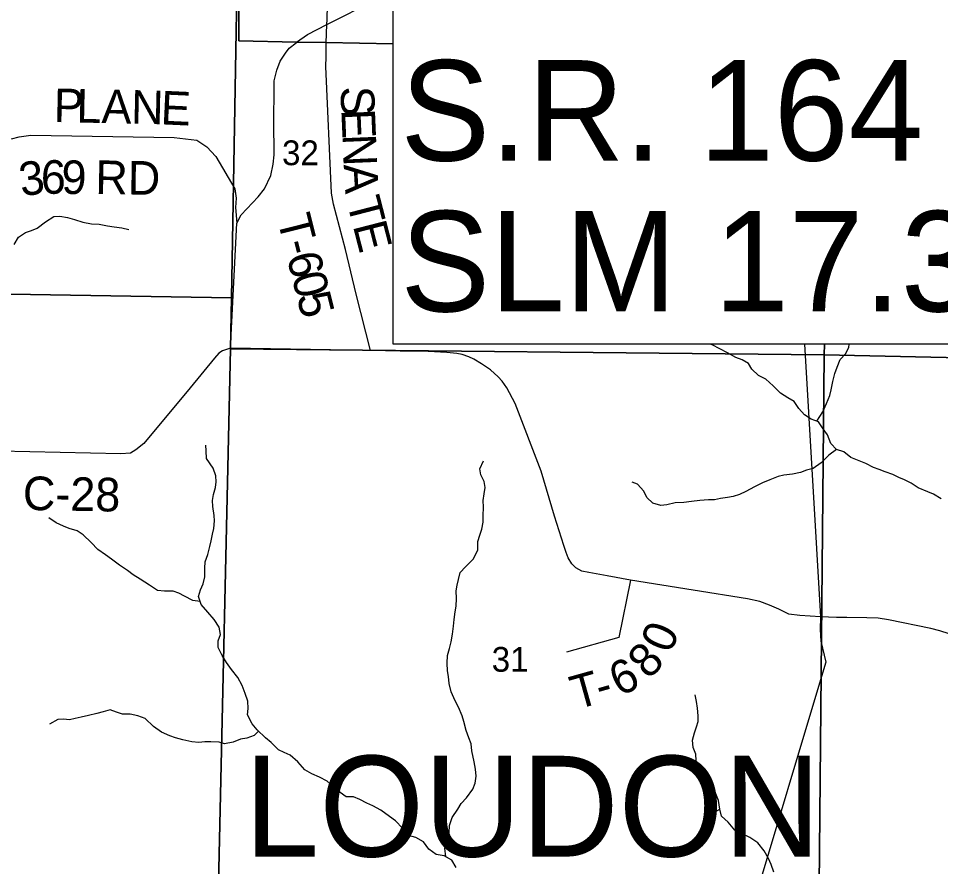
# Model space of a CAD drawing. Extents: x -20.5 to 34, y -66 to 23.9.
# Drawn here: x 5.573 to 7.132, y 17.496 to 18.93 of the extents above; entities that cross this region are included whole.
import ezdxf

# ---------------------------------------------------------------- set-up
doc = ezdxf.new("R2010")
doc.units = 0
for name, color, linetype in [('Default', 7, 'Continuous'), ('GM_X_County_Text', 7, 'Continuous'), ('GM_X_Minor_Lake', 7, 'Continuous'), ('GM_X_Minor_River', 7, 'Continuous'), ('GM_X_Minor_River_Text', 7, 'Continuous'), ('GM_X_Section_Text', 7, 'Continuous'), ('GM_X_State_Location', 7, 'Continuous'), ('GM_X_State_Route', 7, 'Continuous'), ('GM_X_Township_Road_Text', 7, 'Continuous'), ('GM_X_Township_Text', 7, 'Continuous'), ('SH_Text', 7, 'Continuous')]:
    doc.layers.add(name, color=color, linetype=linetype)

msp = doc.modelspace()

# ---------------------------------------------------------------- linework, layer by layer
at = {"layer": 'Default'}
for points in [[(8.3774, 18.8452), (8.7292, 18.8379), (8.9, 18.8361), (8.9, 20.9), (2.1, 20.9), (2.1, 19.024), (2.1138, 19.0238), (2.8866, 19.0123), (2.9847, 19.0125), (3.3332, 19.0103), (5.1839, 18.9738), (5.2343, 18.9736), (5.2893, 18.9731), (5.9456, 18.969), (5.9451, 18.8918), (6.0429, 18.8899), (6.0928, 18.889), (6.2064, 18.8869)], [(6.2064, 18.8869), (6.0928, 18.889), (6.0429, 18.8899), (5.9451, 18.8918), (5.9456, 18.969), (5.2893, 18.9731), (5.2343, 18.9736), (5.1839, 18.9738), (3.3332, 19.0103), (2.9847, 19.0125), (2.8866, 19.0123), (2.8861, 18.9025), (2.8826, 18.5075), (2.8801, 18.0269), (2.88, 18.0245)]]:
    msp.add_lwpolyline(points, dxfattribs=at)
at = {"layer": 'GM_X_County_Text'}
for p, q in [((6.9024, 18.3792), (6.9292, 17.9178)), ((6.9226, 17.7886), (6.6781, 16.9745))]:
    msp.add_line(p, q, dxfattribs=at)
for points in [[(6.0946, 18.9277), (6.0951, 18.9521), (6.0953, 18.9667), (6.0907, 18.9815), (6.0603, 19.0257), (6.0466, 19.0569), (6.0218, 19.0744)], [(6.093, 18.8874), (6.093, 18.8885), (6.0945, 18.9196), (6.0946, 18.9277)], [(6.1683, 18.3682), (6.1436, 18.4633), (6.1256, 18.5392), (6.1054, 18.6158), (6.102, 18.6341), (6.0926, 18.8484), (6.093, 18.865), (6.093, 18.8874)], [(5.5609, 18.7262), (5.5738, 18.7296), (5.5938, 18.7323), (5.8358, 18.7284), (5.8745, 18.7238), (5.8914, 18.7124), (5.9062, 18.696), (5.9388, 18.6418), (5.9411, 18.6258), (5.94, 18.6103), (5.9418, 18.5834)], [(6.6081, 17.9801), (6.5883, 17.8829), (6.4997, 17.8579)], [(6.9292, 17.9178), (6.9287, 17.8963), (6.9296, 17.8766), (6.9329, 17.8649), (6.9384, 17.841), (6.9226, 17.7886)]]:
    msp.add_lwpolyline(points, dxfattribs=at)
at = {"layer": 'GM_X_Minor_Lake'}
for points in [[(4.9304, 19.491), (5.9508, 19.4767), (5.9493, 19.3913), (5.9332, 18.4574), (4.9118, 18.4742)], [(4.9118, 18.4742), (5.9332, 18.4574), (5.9313, 18.3709), (5.9103, 17.4412), (4.9246, 17.4548), (4.898, 17.4556)], [(6.9356, 18.3607), (6.9259, 17.3432), (5.9397, 17.3613), (5.9082, 17.3615), (5.9103, 17.4412), (5.9313, 18.3709)], [(7.9409, 18.3387), (7.9284, 17.3287), (7.0924, 17.3404), (6.9259, 17.3432), (6.9356, 18.3607)]]:
    msp.add_lwpolyline(points, close=True, dxfattribs=at)
for points in [[(6.9358, 18.3792), (6.9356, 18.3607), (5.9313, 18.3709), (5.9332, 18.4574), (5.9493, 19.3913), (6.9446, 19.3763), (6.9427, 19.1628)], [(7.9415, 18.3792), (7.9409, 18.3387), (6.9356, 18.3607), (6.9358, 18.3792)]]:
    msp.add_lwpolyline(points, dxfattribs=at)
at = {"layer": 'GM_X_Minor_River'}
for points in [[(6.7259, 17.649), (6.7273, 17.6343), (6.7301, 17.6256), (6.7356, 17.609), (6.7395, 17.5995), (6.7419, 17.592), (6.7477, 17.5864), (6.7589, 17.5926)], [(6.7589, 17.5926), (6.7568, 17.607), (6.7521, 17.6187), (6.7474, 17.6292), (6.7381, 17.642), (6.7259, 17.649)]]:
    msp.add_lwpolyline(points, dxfattribs=at)
at = {"layer": 'GM_X_Minor_River_Text'}
for points in [[(5.5652, 18.5474), (5.5726, 18.56), (5.5846, 18.5677), (5.5948, 18.5713), (5.6045, 18.5753), (5.6184, 18.5857), (5.6323, 18.5946), (5.6428, 18.5956), (5.6557, 18.5931), (5.6675, 18.5899), (5.6816, 18.5852), (5.696, 18.5823), (5.7093, 18.5818), (5.7233, 18.579), (5.7347, 18.5772), (5.7476, 18.5755), (5.7593, 18.5731)], [(7.1335, 18.1176), (7.1205, 18.1254), (7.1106, 18.129), (7.0946, 18.136), (7.0824, 18.1441), (7.0713, 18.1496), (7.0618, 18.1537), (7.0519, 18.1588), (7.0389, 18.1632), (7.0287, 18.1668), (7.0192, 18.1705), (7.0062, 18.1771), (6.9948, 18.1815), (6.9807, 18.1873), (6.9688, 18.197), (6.9563, 18.2006), (6.9466, 18.2107), (6.9411, 18.2254), (6.9338, 18.2356), (6.926, 18.2476), (6.9135, 18.2519), (6.9024, 18.2597), (6.8924, 18.2702), (6.8846, 18.2822), (6.8739, 18.2881), (6.8617, 18.2963), (6.849, 18.3082), (6.8368, 18.3198), (6.8242, 18.3261), (6.8134, 18.3365), (6.8076, 18.3463), (6.7969, 18.3522), (6.7859, 18.3566), (6.7717, 18.3643), (6.7588, 18.3713), (6.7462, 18.3776), (6.7416, 18.3792)], [(6.9233, 18.2485), (6.9333, 18.2644), (6.9392, 18.2785), (6.945, 18.2922), (6.9471, 18.3018), (6.9503, 18.3158), (6.9535, 18.3295), (6.9572, 18.3402), (6.9626, 18.3528), (6.9716, 18.3628), (6.9771, 18.3731), (6.9776, 18.3792)], [(5.8818, 17.9385), (5.8774, 17.9521), (5.8803, 17.9635), (5.8851, 17.9738), (5.8879, 17.9856), (5.8881, 18), (5.8887, 18.011), (5.893, 18.0232), (5.8966, 18.0366), (5.8987, 18.0465), (5.9008, 18.0575), (5.9029, 18.067), (5.9043, 18.0799), (5.9034, 18.0894), (5.9016, 18.1042), (5.9011, 18.1144), (5.9024, 18.1246), (5.9057, 18.1365), (5.907, 18.1463), (5.9065, 18.1562), (5.9021, 18.169), (5.8905, 18.1855), (5.8899, 18.1988), (5.8898, 18.2083)], [(6.9563, 18.2006), (6.9435, 18.1913), (6.9305, 18.1782), (6.9166, 18.1689), (6.9057, 18.1657), (6.8952, 18.1621), (6.882, 18.1589), (6.8672, 18.1576), (6.8574, 18.1551), (6.8435, 18.1496), (6.8311, 18.1445), (6.8176, 18.1375), (6.803, 18.1296), (6.7924, 18.1249), (6.7815, 18.1214), (6.7717, 18.1197), (6.76, 18.118), (6.7502, 18.1159), (6.7396, 18.1154), (6.7249, 18.1144), (6.7113, 18.1127), (6.698, 18.1114), (6.6833, 18.1104), (6.6693, 18.1071), (6.6591, 18.1062), (6.6458, 18.1102), (6.6355, 18.1195), (6.6304, 18.1304), (6.62, 18.1424), (6.6105, 18.1453)], [(6.2954, 17.5121), (6.2941, 17.5268), (6.3023, 17.5402), (6.3009, 17.5523), (6.3015, 17.5648), (6.3062, 17.5785), (6.3158, 17.5927), (6.3217, 17.6023), (6.3307, 17.6119), (6.3414, 17.6265), (6.3454, 17.6368), (6.3468, 17.6486), (6.3458, 17.6603), (6.3434, 17.6728), (6.3397, 17.6913), (6.3384, 17.7031), (6.3344, 17.7132), (6.3297, 17.7257), (6.3257, 17.7408), (6.3233, 17.7506), (6.317, 17.7653), (6.3115, 17.7759), (6.3045, 17.7909), (6.3012, 17.8053), (6.3003, 17.8167), (6.2986, 17.8265), (6.2977, 17.8394), (6.2986, 17.8523), (6.3015, 17.8645), (6.3047, 17.8755), (6.3068, 17.8884), (6.3085, 17.9021), (6.3094, 17.9131), (6.3111, 17.9261), (6.3129, 17.9359), (6.3134, 17.9488), (6.3132, 17.9617), (6.3146, 17.9712), (6.3167, 17.9811), (6.3199, 17.9929), (6.3289, 18.0026), (6.3423, 18.016), (6.3496, 18.031), (6.3498, 18.0454), (6.353, 18.0557), (6.3567, 18.0663), (6.3584, 18.0777), (6.3586, 18.0884), (6.3591, 18.1032), (6.3589, 18.1145), (6.3603, 18.1259), (6.362, 18.1366), (6.3603, 18.1468), (6.3549, 18.1577), (6.3532, 18.1679), (6.3591, 18.1817)], [(5.8802, 17.9436), (5.8673, 17.9455), (5.8536, 17.9528), (5.8437, 17.958), (5.8342, 17.9613), (5.8198, 17.961), (5.8077, 17.9624), (5.7943, 17.9713), (5.7786, 17.9813), (5.7668, 17.9891), (5.7572, 17.9961), (5.7438, 18.0054), (5.73, 18.0151), (5.7201, 18.0225), (5.7067, 18.0318), (5.6955, 18.0437), (5.6821, 18.0564), (5.6718, 18.0631), (5.6585, 18.0674), (5.649, 18.0711), (5.6364, 18.077), (5.6238, 18.0851)], [(6.3132, 17.4941), (6.3054, 17.5065), (6.2928, 17.5135), (6.2792, 17.5159), (6.2665, 17.5248), (6.258, 17.5376), (6.2447, 17.5446), (6.2325, 17.5482), (6.2225, 17.5602), (6.2102, 17.5729), (6.2002, 17.58), (6.1857, 17.5911), (6.1723, 17.5981), (6.1621, 17.6029), (6.1498, 17.6092), (6.1392, 17.6135), (6.1267, 17.6137), (6.1167, 17.6208), (6.1049, 17.6309), (6.0949, 17.6398), (6.0819, 17.6468), (6.069, 17.6523), (6.0571, 17.6593), (6.0452, 17.6728), (6.0322, 17.684), (6.0222, 17.6884), (6.0127, 17.6928), (6, 17.7051), (5.9905, 17.7133), (5.9763, 17.7268), (5.9682, 17.7369), (5.9603, 17.7523), (5.9613, 17.7629), (5.9604, 17.7751), (5.956, 17.7883), (5.9509, 17.8015), (5.9435, 17.815), (5.9331, 17.8285), (5.9246, 17.8405), (5.9172, 17.8525), (5.9106, 17.8657), (5.9104, 17.8771), (5.9144, 17.8878), (5.9123, 17.9006), (5.9038, 17.9134), (5.893, 17.9258), (5.8818, 17.9385)], [(6.8502, 17.4863), (6.8459, 17.4991), (6.8416, 17.5089), (6.8338, 17.5221), (6.8234, 17.5356), (6.8096, 17.5448), (6.7967, 17.5507), (6.7841, 17.557), (6.7733, 17.5708), (6.7618, 17.5809), (6.7589, 17.5926), (6.7568, 17.607), (6.7521, 17.6187), (6.7474, 17.6292), (6.7381, 17.642), (6.7259, 17.649), (6.7216, 17.6607), (6.7187, 17.6751), (6.7182, 17.6857), (6.7138, 17.697), (6.7129, 17.7091), (6.7161, 17.7217), (6.7194, 17.7316), (6.7222, 17.7411), (6.7225, 17.7506), (6.7211, 17.7635), (6.7195, 17.7745), (6.7174, 17.7858)], [(5.9789, 17.7242), (5.9715, 17.7172), (5.9591, 17.7128), (5.9481, 17.7108), (5.9357, 17.706), (5.9214, 17.7032), (5.9119, 17.7057), (5.8979, 17.7066), (5.888, 17.7064), (5.8778, 17.7051), (5.8657, 17.7065), (5.8505, 17.7097), (5.8383, 17.7133), (5.8285, 17.7165), (5.8147, 17.7228), (5.8013, 17.7324), (5.7868, 17.7459), (5.7746, 17.7506), (5.7617, 17.7531), (5.7484, 17.7532), (5.7385, 17.7565), (5.7275, 17.7605), (5.7158, 17.7573), (5.7053, 17.7545), (5.6913, 17.7509), (5.6789, 17.748), (5.6687, 17.746), (5.6589, 17.7439), (5.649, 17.7445), (5.6392, 17.744), (5.6253, 17.7362)]]:
    msp.add_lwpolyline(points, dxfattribs=at)
at = {"layer": 'GM_X_State_Route'}
for points in [[(6.0422, 18.8887), (6.0431, 18.8894), (6.0615, 18.9024), (6.0945, 18.9196), (6.1772, 18.9617), (6.1887, 18.9656), (6.1991, 18.9679), (6.2064, 18.9689)], [(5.9311, 18.3724), (5.9418, 18.5834), (5.9493, 18.5975), (5.9778, 18.6281), (5.9886, 18.6418), (5.9993, 18.6641), (6.0036, 18.6833), (6.0054, 18.6992), (6.0048, 18.756), (6.0051, 18.8103), (6.0052, 18.824), (6.0095, 18.8424), (6.0152, 18.8573), (6.0241, 18.8712), (6.0308, 18.8796), (6.0422, 18.8887)], [(7.1468, 17.8888), (7.1309, 17.8941), (7.1159, 17.8979), (7.0441, 17.913), (7.0269, 17.9156), (7.0077, 17.9162), (6.9738, 17.9165), (6.9561, 17.9168), (6.9292, 17.9178), (6.8941, 17.9198), (6.8756, 17.9226), (6.8586, 17.9307), (6.8432, 17.9377), (6.8264, 17.9436), (6.8057, 17.9483), (6.714, 17.9632), (6.6081, 17.9801), (6.5683, 17.987), (6.5373, 17.9928), (6.5256, 17.9953), (6.5154, 18.0009), (6.5087, 18.0074), (6.5025, 18.0174), (6.499, 18.0265), (6.4952, 18.0384), (6.4791, 18.0878), (6.457, 18.1639), (6.4129, 18.2786), (6.3989, 18.3053), (6.3907, 18.3165), (6.3843, 18.3236), (6.3713, 18.3353), (6.3561, 18.3455), (6.3427, 18.3533), (6.3343, 18.3574), (6.3232, 18.3612), (6.3139, 18.3632), (6.2974, 18.3649), (6.2658, 18.3664), (6.2181, 18.3671), (6.1683, 18.3682), (5.9311, 18.3724), (5.9176, 18.3679), (5.9115, 18.3638), (5.9044, 18.3553), (5.8631, 18.3052), (5.7845, 18.2107), (5.7712, 18.2), (5.7619, 18.1946), (5.746, 18.1933), (5.4374, 18.2004)]]:
    msp.add_lwpolyline(points, dxfattribs=at)
at = {"layer": 'SH_Text'}
msp.add_lwpolyline([(6.2064, 19.1628), (8.3774, 19.1628), (8.3774, 18.3792), (6.2064, 18.3792)], close=True, dxfattribs=at)

# ---------------------------------------------------------------- texts
at = {"layer": 'GM_X_Section_Text'}
for s, height, rotation, p in [('P', 0.0568, 358.8311, (5.6319, 18.7546)), ('S', 0.0568, 272.3954, (6.1171, 18.8142)), ('L', 0.0568, 358.8321, (5.6702, 18.7538)), ('A', 0.0568, 358.8306, (5.7127, 18.7529)), ('N', 0.0568, 358.7595, (5.7627, 18.7519)), ('E', 0.0568, 357.3891, (5.8123, 18.7508)), ('E', 0.0568, 272.3982, (6.1187, 18.7759)), ('N', 0.0568, 272.4002, (6.1205, 18.7334)), ('3', 0.0568, 8.1555, (5.5778, 18.6287)), ('6', 0.0568, 359.3339, (5.6102, 18.6335)), ('9', 0.0568, 359.2012, (5.6451, 18.6331)), ('RD', 0.05682, 359.0118, (5.7023, 18.6331)), ('A', 0.0568, 273.2783, (6.1227, 18.6825)), ('T', 0.0568, 284.521, (6.1274, 18.6206)), ('T', 0.0568, 284.0888, (6.0098, 18.5914)), ('E', 0.0568, 284.4229, (6.138, 18.5795)), ('-', 0.0568, 284.099, (6.0202, 18.5502)), ('6', 0.0568, 284.1255, (6.0258, 18.5278)), ('0', 0.0568, 284.1938, (6.0343, 18.494)), ('5', 0.0568, 284.2607, (6.0428, 18.4603)), ('0', 0.0568, 66.6286, (6.6752, 17.854)), ('8', 0.0568, 46.2341, (6.6389, 17.8105)), ('6', 0.0568, 25.8396, (6.5896, 17.7823)), ('T', 0.0568, 15.6424, (6.5159, 17.7606)), ('-', 0.0568, 15.6424, (6.5568, 17.7721))]:
    msp.add_text(s, height=height, rotation=rotation, dxfattribs=at).set_placement(p)
at = {"layer": 'GM_X_State_Location'}
msp.add_text('LOUDON', height=0.17045, rotation=0, dxfattribs=at).set_placement((5.9546, 17.5124))
at = {"layer": 'GM_X_Township_Road_Text'}
msp.add_text('C-28', height=0.05682, rotation=358.9708, dxfattribs=at).set_placement((5.5797, 18.0987))
at = {"layer": 'GM_X_Township_Text'}
for s, p in [('32', (6.0185, 18.6816)), ('31', (6.3731, 17.825))]:
    msp.add_text(s, height=0.04186, rotation=0, dxfattribs=at).set_placement(p)
at = {"layer": 'SH_Text'}
for s, p in [('S.R. 164', (6.2187, 18.6892)), ('SLM 17.32', (6.2187, 18.4342))]:
    msp.add_text(s, height=0.17, dxfattribs=at).set_placement(p)

doc.saveas('drawing.dxf')
